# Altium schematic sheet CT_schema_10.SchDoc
size 287 x 160 mm
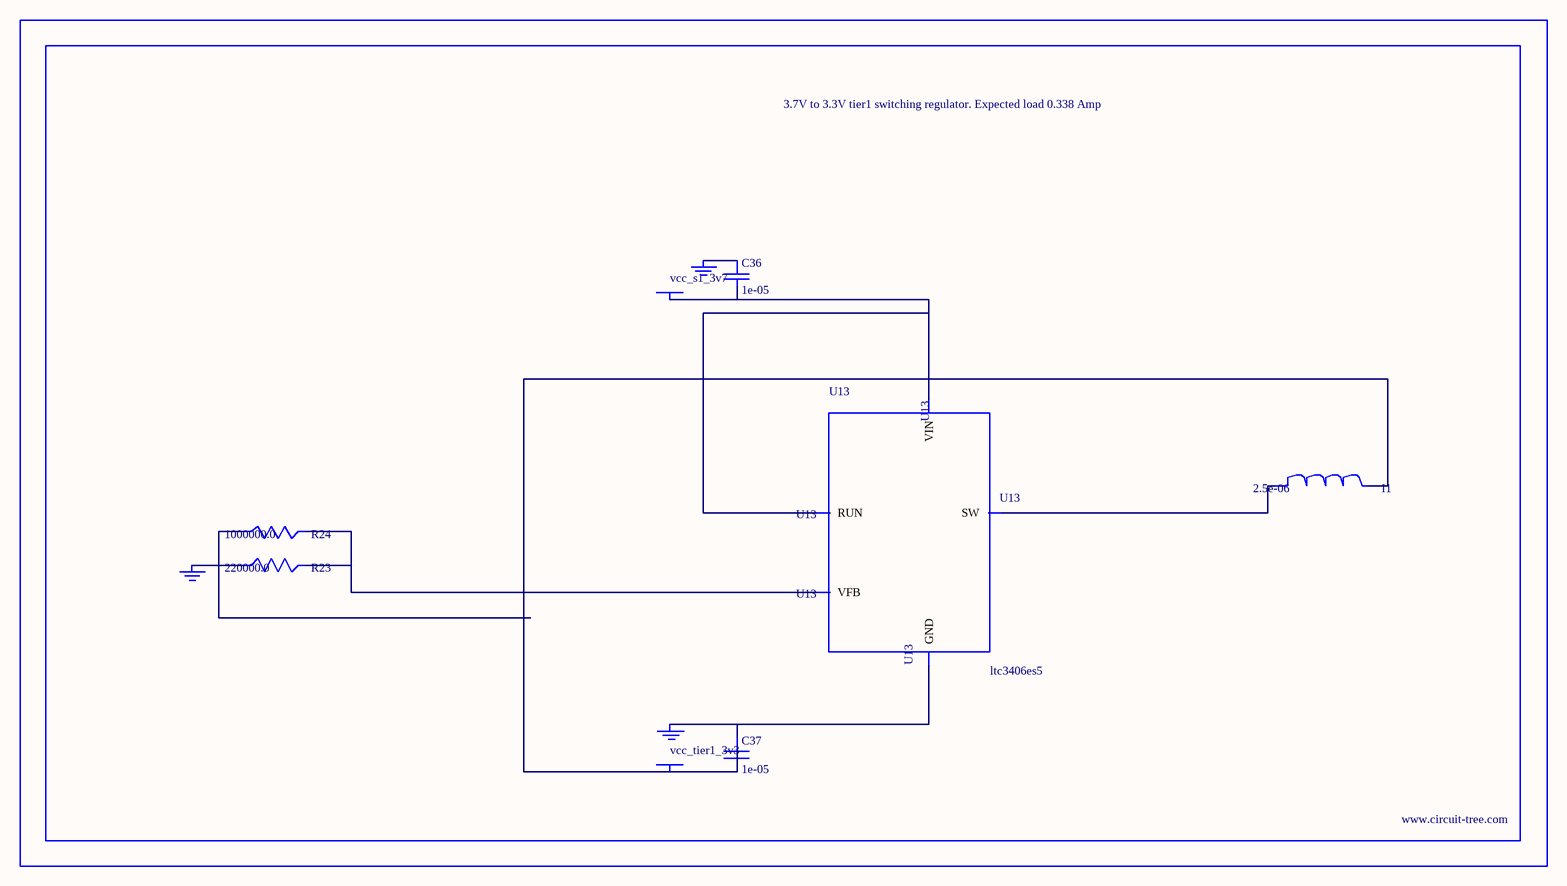
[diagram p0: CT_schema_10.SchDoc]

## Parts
BORDER9  (no value)
C36  1e-05  [C0805]
C37  1e-05  [C0805]
GND_INSTANCE_9_0  (no value)
GND_INSTANCE_9_1  (no value)
GND_INSTANCE_9_2  (no value)
I1  2.5e-06  [DR1040]
POWER_INSTANCE_9_0  vcc_tier1_3v3
POWER_INSTANCE_9_1  vcc_s1_3v7
R23  220000.0  [R0603]
R24  1000000.0  [R0603]
U13  ltc3406es5  [TSOT-23-5]

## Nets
NetC36_1: C36.1 GND_INSTANCE_9_1.0(GND)
NetC36_2: C36.2 POWER_INSTANCE_9_1.0(PWR) U13.1(RUN) U13.4(VIN)
NetC37_1: C37.1 GND_INSTANCE_9_0.0(GND) U13.2(GND)
NetC37_2: C37.2 I1.2 POWER_INSTANCE_9_0.0(PWR) R24.1
NetGND_INSTANCE_9_2_0: GND_INSTANCE_9_2.0(GND) R23.1
NetI1_1: I1.1 U13.3(SW)
NetR23_2: R23.2 R24.2 U13.5(VFB)

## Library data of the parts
BORDER9 = BORDER_PAGE9
C36 C37 = C0805C106K8RACTU
GND_INSTANCE_9_0-GND_INSTANCE_9_2 = GND
I1 = DR1040-2R5-R
POWER_INSTANCE_9_0 POWER_INSTANCE_9_1 = PWR
R23 = RC0603JR-07220KL
R24 = RC0603JR-071ML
